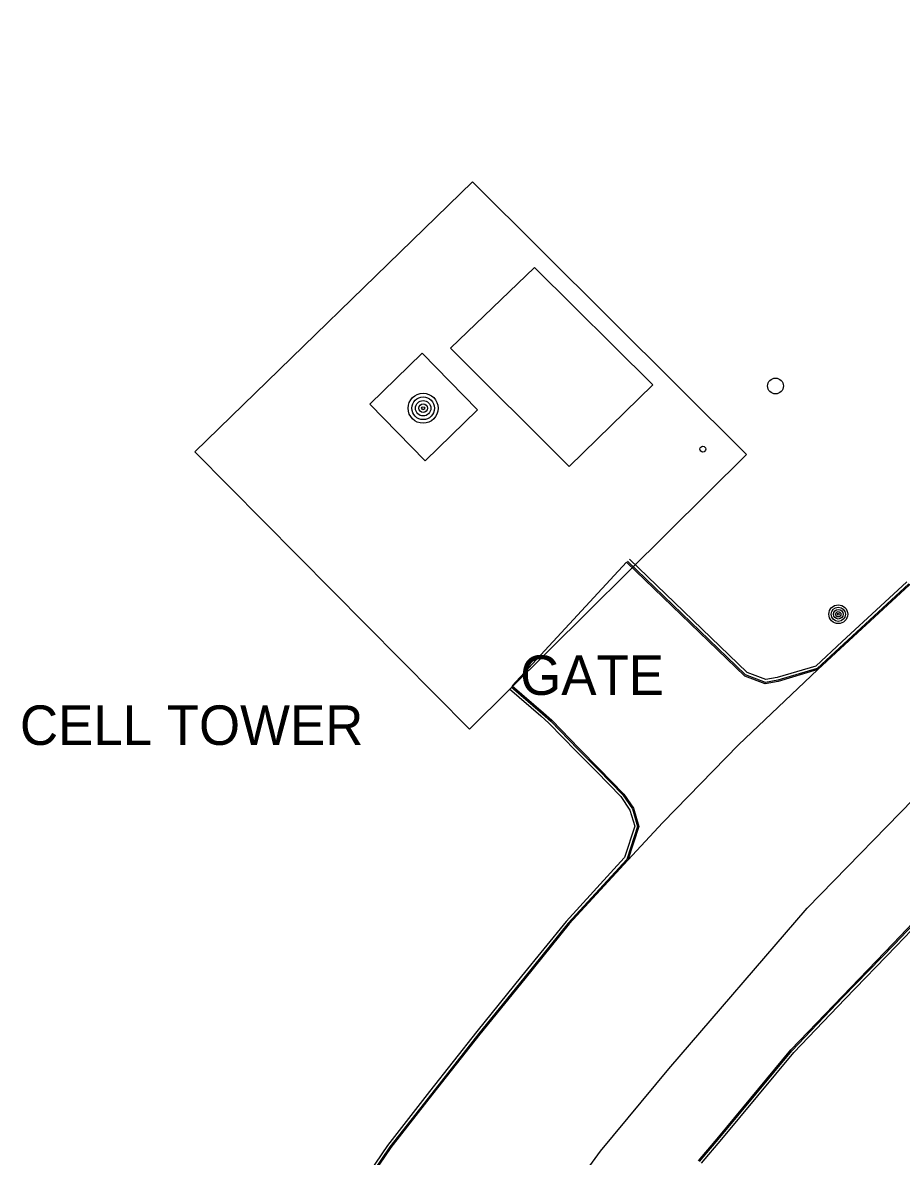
# Model space of a CAD drawing. Extents: x 368532 to 392481, y 10654822 to 10676899.
# Drawn here: x 374388.1 to 374499.3, y 10670907.2 to 10671050.7 of the extents above; entities that cross this region are included whole.
import ezdxf

# ---------------------------------------------------------------- set-up
doc = ezdxf.new("R2010")
doc.units = 0
for name, color, linetype in [('p_dtm slab', 7, 'Continuous'), ('p_road - paved curb', 7, 'Continuous'), ('p_road general road feature', 7, 'Continuous'), ('p_road paint stripe', 7, 'Continuous'), ('p_structure building', 7, 'Continuous'), ('p_structure fence', 7, 'Continuous'), ('p_structure unidentified', 7, 'Continuous'), ('p_utility general pole', 7, 'Continuous'), ('p_utility guy anchor', 7, 'Continuous')]:
    doc.layers.add(name, color=color, linetype=linetype)

msp = doc.modelspace()

# ---------------------------------------------------------------- linework, layer by layer
at = {"layer": 'p_dtm slab'}
for p, q in [((374438.63, 10671008.89), (374432, 10671002.43)), ((374445.63, 10671001.71), (374438.63, 10671008.89)), ((374432, 10671002.43), (374439, 10670995.25)), ((374439, 10670995.25), (374445.63, 10671001.71))]:
    msp.add_line(p, q, dxfattribs=at)
at = {"layer": 'p_road - paved curb'}
for p, q in [((374499.98, 10670979.93), (374496.65, 10670976.86)), ((374500.22, 10670979.67), (374496.89, 10670976.6)), ((374496.65, 10670976.86), (374491.78, 10670972.37)), ((374496.89, 10670976.6), (374492.02, 10670972.11)), ((374491.78, 10670972.37), (374488.45, 10670969.28)), ((374492.02, 10670972.11), (374488.63, 10670968.96)), ((374488.71, 10670968.83), (374478.66, 10670959.32)), ((374478.66, 10670959.32), (374469.1, 10670949.47)), ((374469.1, 10670949.47), (374464.65, 10670944.73)), ((374464.21, 10670944.99), (374456.85, 10670936.97)), ((374464.52, 10670944.81), (374457.12, 10670936.74)), ((374464.65, 10670944.73), (374457.23, 10670936.64)), ((374498.37, 10670934.06), (374503.47, 10670939.42)), ((374498.62, 10670933.81), (374503.71, 10670939.17)), ((374456.85, 10670936.97), (374451.22, 10670930.03)), ((374457.12, 10670936.74), (374451.49, 10670929.8)), ((374457.23, 10670936.64), (374451.61, 10670929.71)), ((374491.93, 10670927.42), (374498.37, 10670934.06)), ((374492.18, 10670927.17), (374498.62, 10670933.81)), ((374451.22, 10670930.03), (374445.53, 10670923.01)), ((374451.49, 10670929.8), (374445.8, 10670922.79)), ((374451.61, 10670929.71), (374445.92, 10670922.7)), ((374485.4, 10670920.59), (374491.93, 10670927.42)), ((374485.66, 10670920.36), (374492.18, 10670927.17)), ((374445.53, 10670923.01), (374439.56, 10670915.42)), ((374445.8, 10670922.79), (374439.83, 10670915.2)), ((374445.92, 10670922.7), (374439.95, 10670915.11)), ((374476.3, 10670909.61), (374485.4, 10670920.59)), ((374476.57, 10670909.39), (374485.66, 10670920.36)), ((374439.56, 10670915.42), (374434.25, 10670908.62)), ((374439.83, 10670915.2), (374434.53, 10670908.42)), ((374439.95, 10670915.11), (374434.65, 10670908.33)), ((374434.25, 10670908.62), (374428.88, 10670900.72)), ((374473.73, 10670906.58), (374476.3, 10670909.61)), ((374474, 10670906.36), (374476.57, 10670909.39)), ((374434.53, 10670908.42), (374429.17, 10670900.52)), ((374434.65, 10670908.33), (374429.29, 10670900.44))]:
    msp.add_line(p, q, dxfattribs=at)
for points in [[(374580.8, 10671050.71), (374576.29, 10671044.81), (374573.29, 10671042.02), (374563.6, 10671033.74), (374557.37, 10671028.48), (374551.21, 10671023.25), (374546.14, 10671018.96), (374540.64, 10671014.26), (374534.51, 10671009.06), (374528.61, 10671004.05), (374522.59, 10670998.94), (374517.28, 10670994.4), (374513.25, 10670990.98), (374507.76, 10670986.33), (374500.32, 10670979.56), (374496.99, 10670976.49), (374492.12, 10670972), (374488.71, 10670968.83)], [(374473.61, 10670906.67), (374476.19, 10670909.71), (374485.29, 10670920.69), (374491.82, 10670927.52), (374498.26, 10670934.16), (374503.36, 10670939.53)]]:
    msp.add_lwpolyline(points, dxfattribs=at)
at = {"layer": 'p_road general road feature'}
for p, q in [((374450, 10670966.77), (374464.5, 10670982.44)), ((374479.49, 10670968.02), (374464.5, 10670982.44)), ((374479.57, 10670968.15), (374464.6, 10670982.55)), ((374479.76, 10670968.45), (374464.85, 10670982.8)), ((374488.45, 10670969.28), (374483.56, 10670967.82)), ((374488.63, 10670968.96), (374483.64, 10670967.48)), ((374488.71, 10670968.83), (374483.67, 10670967.33)), ((374482.06, 10670967.05), (374479.49, 10670968.02)), ((374482.07, 10670967.2), (374479.57, 10670968.15)), ((374482.11, 10670967.57), (374479.76, 10670968.45)), ((374483.67, 10670967.33), (374482.06, 10670967.05)), ((374483.64, 10670967.48), (374482.07, 10670967.2)), ((374483.56, 10670967.82), (374482.11, 10670967.57)), ((374449.67, 10670966.39), (374453.64, 10670962.98)), ((374449.9, 10670966.66), (374453.87, 10670963.25)), ((374450, 10670966.77), (374453.97, 10670963.36)), ((374453.87, 10670963.25), (374454.92, 10670962.31)), ((374453.97, 10670963.36), (374455.02, 10670962.42)), ((374453.64, 10670962.98), (374454.67, 10670962.06)), ((374454.67, 10670962.06), (374458.13, 10670958.5)), ((374454.92, 10670962.31), (374458.38, 10670958.74)), ((374455.02, 10670962.42), (374458.49, 10670958.85)), ((374458.38, 10670958.74), (374460.94, 10670956.16)), ((374458.49, 10670958.85), (374461.05, 10670956.27)), ((374458.13, 10670958.5), (374460.69, 10670955.92)), ((374460.69, 10670955.92), (374463.77, 10670952.76)), ((374460.94, 10670956.16), (374464.04, 10670952.98)), ((374461.05, 10670956.27), (374464.16, 10670953.08)), ((374464.04, 10670952.98), (374465.25, 10670951.22)), ((374464.16, 10670953.08), (374465.39, 10670951.28)), ((374463.77, 10670952.76), (374464.93, 10670951.06)), ((374464.93, 10670951.06), (374465.54, 10670949)), ((374465.25, 10670951.22), (374465.9, 10670948.99)), ((374465.39, 10670951.28), (374466.06, 10670948.99)), ((374465.54, 10670949), (374464.24, 10670945.07)), ((374465.9, 10670948.99), (374464.56, 10670944.92)), ((374466.06, 10670948.99), (374464.65, 10670944.73)), ((374464.24, 10670945.07), (374464.21, 10670944.99)), ((374464.56, 10670944.92), (374464.52, 10670944.81))]:
    msp.add_line(p, q, dxfattribs=at)
at = {"layer": 'p_road paint stripe'}
for p, q in [((374487.38, 10670938.63), (374503.21, 10670954.91)), ((374469.87, 10670918.31), (374487.38, 10670938.63)), ((374461.18, 10670907.89), (374469.87, 10670918.31)), ((374442.16, 10670881.66), (374461.18, 10670907.89))]:
    msp.add_line(p, q, dxfattribs=at)
at = {"layer": 'p_structure building'}
msp.add_lwpolyline([(374467.81, 10671004.87), (374452.84, 10671019.72), (374442.2, 10671009.52), (374457.23, 10670994.53)], close=True, dxfattribs=at)
at = {"layer": 'p_structure fence'}
for p, q in [((374409.86, 10670996.39), (374444.98, 10671030.58)), ((374444.98, 10671030.58), (374479.68, 10670996.05)), ((374444.6, 10670961.31), (374409.86, 10670996.39)), ((374479.68, 10670996.05), (374444.6, 10670961.31))]:
    msp.add_line(p, q, dxfattribs=at)
at = {"layer": 'p_structure unidentified'}
msp.add_circle((374474.16, 10670996.74), 0.375, dxfattribs=at)
at = {"layer": 'p_utility general pole'}
for centre, radius in [((374438.75, 10671001.91), 1.9), ((374438.75, 10671001.91), 1.44), ((374438.75, 10671001.91), 0.973), ((374438.75, 10671001.91), 0.539), ((374438.75, 10671001.91), 0.192), ((374491.3, 10670975.84), 1.19), ((374491.3, 10670975.84), 0.901), ((374491.3, 10670975.84), 0.608), ((374491.3, 10670975.84), 0.337), ((374491.3, 10670975.84), 0.12)]:
    msp.add_circle(centre, radius, dxfattribs=at)
at = {"layer": 'p_utility guy anchor'}
msp.add_circle((374483.35, 10671004.73), 1, dxfattribs=at)

# ---------------------------------------------------------------- texts
at = {"layer": 'p_dtm slab'}
msp.add_text('CELL TOWER ', height=5, dxfattribs=at).set_placement((374387.71, 10670959.3))
at = {"layer": 'p_structure fence'}
msp.add_text(' GATE', height=5, dxfattribs=at).set_placement((374449.18, 10670965.63))

doc.saveas('drawing.dxf')
